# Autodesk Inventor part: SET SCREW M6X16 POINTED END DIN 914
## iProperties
IsCustomPart: 1
Created: 2006-02
Part Number: SET SCREW M6X16 POINTED END DIN 914
Material: Steel, Mild
Description: Hexagon Socket Set Screw
Document SubType Name: Modeling
Standard: DIN 914
Designer: Andy Moles
Standards Organization: DIN
Language: en-US
Size Designation: M6 x 16
Categories: <MemberInstance><Categories><Category DisplayName="Fasteners" InternalName="e4da775c-781d-43d5-af7c-5136215cf5a6" Mnemonic="FSTN"><Category DisplayName="Bolts"
Density: 1 g/cm^3
Author: Andy Moles
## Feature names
1. Body [Revolution]
2. Slot [Extrusion]
3. Chamfer1
4. Chamfer2
